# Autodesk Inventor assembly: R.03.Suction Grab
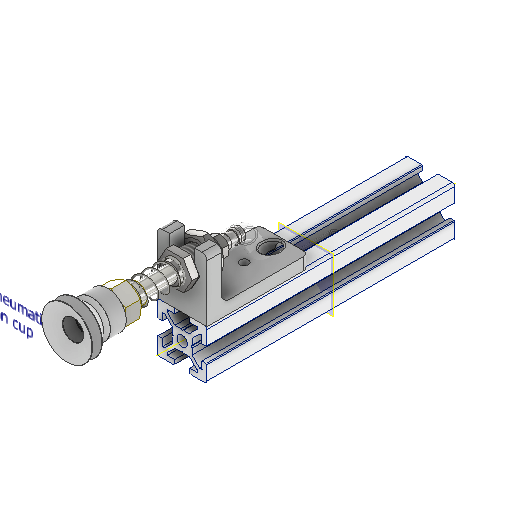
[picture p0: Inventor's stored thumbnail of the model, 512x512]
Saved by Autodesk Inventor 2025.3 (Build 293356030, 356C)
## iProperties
Created: 2021-02
Part Number: R.03.Suction Grab
Document SubType Name: Assembly
Designer: Михальчик
Author: Михальчик
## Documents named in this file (11)
- C:\Users\R5800u\Desktop\robot_riduttore_cicloidale2\Workgroups\NotInProject\ventosa_20mm.iam
- C:\Users\R5800u\Desktop\robot_riduttore_cicloidale2\Workgroups\NotInProject\R.03.01.Cup.ipt
- C:\Users\R5800u\Desktop\robot_riduttore_cicloidale2\Workgroups\NotInProject\R.03.02.Tube.ipt
- C:\Users\R5800u\Desktop\robot_riduttore_cicloidale2\Workgroups\NotInProject\Compress Spring11.ipt
- C:\Users\R5800u\Desktop\robot_riduttore_cicloidale2\Workgroups\NotInProject\R.03.04.Fitting.ipt
- C:\Users\R5800u\Desktop\robot_riduttore_cicloidale2\Workgroups\NotInProject\DIN 3771 - 5 x 1,8 - N - NBR 70(2).ipt
- C:\Users\R5800u\Desktop\robot_riduttore_cicloidale2\Workgroups\NotInProject\R.03.05.Interface.ipt
- C:\Users\R5800u\Desktop\robot_riduttore_cicloidale2\Workgroups\NotInProject\R.03.06.Nut.ipt
- C:\Users\R5800u\Desktop\robot_riduttore_cicloidale2\Workgroups\NotInProject\blocco_ventosa_profilato.ipt
- C:\Users\R5800u\Desktop\robot_riduttore_cicloidale2\Workgroups\NotInProject\tubo_silicone.ipt
- C:\Users\R5800u\Desktop\robot_riduttore_cicloidale2\Workgroups\NotInProject\tslot-20x20-100mm.ipt
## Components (10 placed, 10 different names)
1. R.03.01.Cup:1 — Mate:1, Mate:2
2. R.03.02.Tube:1 — Mate:1, Mate:2, Mate:3, Flush:1, Mate:4, Mate:6, Rigido:1
3. R.03.03.Spring:1 — Mate:3, Flush:1, Mate:7
4. R.03.04.Fitting:1 — Mate:4, Rigido:1, Allineato:4
5. DIN 3771 - 5 x 1,8 - N - NBR 70(2):1 — Rotazionale:1
6. R.03.05.Interface:1 — Mate:6, Mate:7, Mate:8, Rotazionale:1, Rotazionale:2, Angolo:2
7. R.03.06.Nut:1 — Mate:8, Coincidente:9
8. blocco_ventosa_profilato:1 — Coincidente:9, Angolo:1, Coincidente:10, Allineato:2, Allineato:3, Rotazionale:2, Angolo:2
9. tslot-20x20-100mm:1 — Coincidente:10, Allineato:2, Allineato:3
10. tubo_silicone:1 — Allineato:4
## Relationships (18: Mate 9, Flush 4, RevoluteJoint 2, Angle 2, WeldJoint 1)
- Mate:1: R.03.01.Cup:1 ↔ R.03.02.Tube:1
- Mate:2: R.03.01.Cup:1 ↔ R.03.02.Tube:1
- Mate:3: R.03.02.Tube:1 ↔ R.03.03.Spring:1
- Flush:1: R.03.02.Tube:1 ↔ R.03.03.Spring:1
- Mate:4: R.03.02.Tube:1 ↔ R.03.04.Fitting:1
- Mate:6: R.03.02.Tube:1 ↔ R.03.05.Interface:1
- Mate:7: R.03.03.Spring:1 ↔ R.03.05.Interface:1
- Mate:8: R.03.05.Interface:1 ↔ R.03.06.Nut:1
- Rotazionale:1 [RevoluteJoint]: DIN 3771 - 5 x 1,8 - N - NBR 70(2):1 ↔ R.03.05.Interface:1
- Rigido:1 [WeldJoint]: R.03.02.Tube:1 ↔ R.03.04.Fitting:1
- Coincidente:9 [Mate]: R.03.06.Nut:1 ↔ blocco_ventosa_profilato:1
- Angolo:1 [Angle]: blocco_ventosa_profilato:1
- Coincidente:10 [Mate]: blocco_ventosa_profilato:1 ↔ tslot-20x20-100mm:1
- Allineato:2 [Flush]: blocco_ventosa_profilato:1 ↔ tslot-20x20-100mm:1
- Allineato:3 [Flush]: blocco_ventosa_profilato:1 ↔ tslot-20x20-100mm:1
- Allineato:4 [Flush]: R.03.04.Fitting:1 ↔ tubo_silicone:1
- Rotazionale:2 [RevoluteJoint]: R.03.05.Interface:1 ↔ blocco_ventosa_profilato:1
- Angolo:2 [Angle]: R.03.05.Interface:1 ↔ blocco_ventosa_profilato:1
